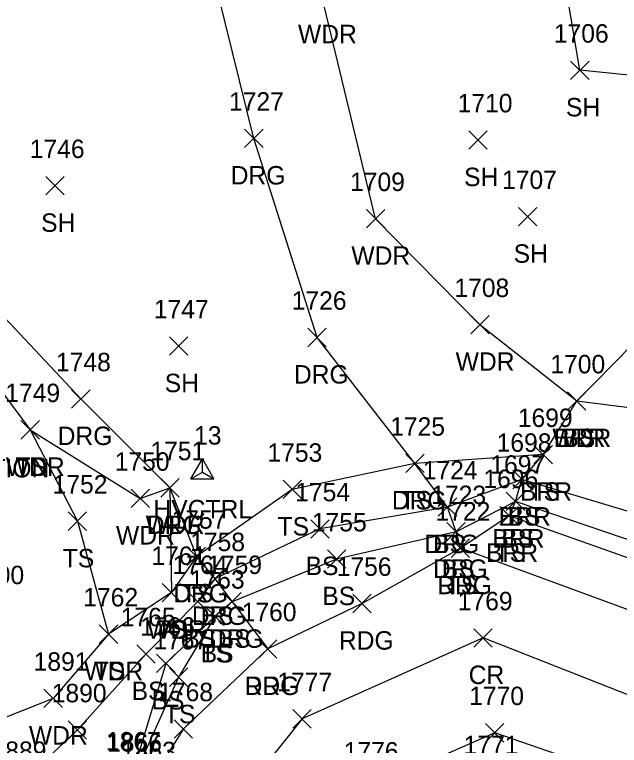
# Model space of a CAD drawing. Extents: x 1600281 to 1602254, y 862855 to 863227.
# Drawn here: x 1602048 to 1602113.6, y 863101.9 to 863181.1 of the extents above; entities that cross this region are included whole.
import ezdxf

# ---------------------------------------------------------------- set-up
doc = ezdxf.new("R2010")
doc.units = 0
for name, color, linetype in [('C_A', 7, 'Continuous'), ('C_I', 7, 'Continuous'), ('CPSM', 7, 'Continuous'), ('L_A', 7, 'Continuous'), ('L_I', 7, 'Continuous'), ('L_TIC', 7, 'Continuous'), ('LABL', 7, 'Continuous'), ('LAWA', 7, 'Continuous'), ('LELB', 7, 'Continuous'), ('LSOGP', 7, 'Continuous'), ('P_A', 7, 'Continuous'), ('P_I', 7, 'Continuous'), ('P_TIC', 7, 'Continuous'), ('PEU', 7, 'Continuous'), ('PRC', 7, 'Continuous'), ('R_A', 7, 'Continuous'), ('R_I', 7, 'Continuous'), ('R_TIC', 7, 'Continuous'), ('RDG', 7, 'Continuous')]:
    doc.layers.add(name, color=color, linetype=linetype)

msp = doc.modelspace()

# ---------------------------------------------------------------- linework, layer by layer
at = {"layer": 'CPSM'}
for p, q in [((1602067.085, 863130.751), (1602068.335, 863132.916)), ((1602069.585, 863130.751), (1602068.335, 863132.916)), ((1602068.336, 863131.472), (1602068.335, 863132.916)), ((1602067.085, 863130.751), (1602068.336, 863131.472)), ((1602068.336, 863131.472), (1602068.336, 863131.472)), ((1602068.336, 863131.472), (1602069.585, 863130.751)), ((1602067.085, 863130.751), (1602069.585, 863130.751))]:
    msp.add_line(p, q, dxfattribs=at)
at = {"layer": 'L_TIC'}
for points in [[(1602108.275, 863174.062), (1602110.275, 863176.062)], [(1602110.275, 863174.062), (1602108.275, 863176.062)], [(1602097.23, 863166.5), (1602099.23, 863168.5)], [(1602099.23, 863166.5), (1602097.23, 863168.5)], [(1602051.363, 863161.543), (1602053.363, 863163.543)], [(1602053.363, 863161.543), (1602051.363, 863163.543)], [(1602086.128, 863157.967), (1602088.128, 863159.967)], [(1602088.128, 863157.967), (1602086.128, 863159.967)], [(1602102.607, 863158.19), (1602104.607, 863160.19)], [(1602104.607, 863158.19), (1602102.607, 863160.19)], [(1602097.439, 863146.474), (1602099.439, 863148.474)], [(1602099.439, 863146.474), (1602097.439, 863148.474)], [(1602064.765, 863144.155), (1602066.765, 863146.155)], [(1602066.765, 863144.155), (1602064.765, 863146.155)], [(1602107.93, 863138.196), (1602109.93, 863140.196)], [(1602109.93, 863138.196), (1602107.93, 863140.196)], [(1602107.93, 863138.196), (1602109.93, 863140.196)], [(1602109.93, 863138.196), (1602107.93, 863140.196)], [(1602107.93, 863138.196), (1602109.93, 863140.196)], [(1602109.93, 863138.196), (1602107.93, 863140.196)], [(1602048.66, 863135.076), (1602050.66, 863137.076)], [(1602050.66, 863135.076), (1602048.66, 863137.076)], [(1602048.66, 863135.076), (1602050.66, 863137.076)], [(1602050.66, 863135.076), (1602048.66, 863137.076)], [(1602104.293, 863132.383), (1602106.293, 863134.383)], [(1602106.293, 863132.383), (1602104.293, 863134.383)], [(1602104.293, 863132.383), (1602106.293, 863134.383)], [(1602106.293, 863132.383), (1602104.293, 863134.383)], [(1602090.394, 863131.436), (1602092.394, 863133.436)], [(1602092.394, 863131.436), (1602090.394, 863133.436)], [(1602101.988, 863129.687), (1602103.988, 863131.687)], [(1602103.988, 863129.687), (1602101.988, 863131.687)], [(1602101.988, 863129.687), (1602103.988, 863131.687)], [(1602103.988, 863129.687), (1602101.988, 863131.687)], [(1602063.822, 863128.779), (1602065.822, 863130.779)], [(1602065.822, 863128.779), (1602063.822, 863130.779)], [(1602077.084, 863128.61), (1602079.084, 863130.61)], [(1602079.084, 863128.61), (1602077.084, 863130.61)], [(1602060.607, 863127.634), (1602062.607, 863129.634)], [(1602062.607, 863127.634), (1602060.607, 863129.634)], [(1602101.3, 863127.31), (1602103.3, 863129.31)], [(1602103.3, 863127.31), (1602101.3, 863129.31)], [(1602101.3, 863127.31), (1602103.3, 863129.31)], [(1602103.3, 863127.31), (1602101.3, 863129.31)], [(1602093.922, 863126.701), (1602095.922, 863128.701)], [(1602095.922, 863126.701), (1602093.922, 863128.701)], [(1602100.608, 863125.756), (1602102.608, 863127.756)], [(1602102.608, 863125.756), (1602100.608, 863127.756)], [(1602100.608, 863125.756), (1602102.608, 863127.756)], [(1602102.608, 863125.756), (1602100.608, 863127.756)], [(1602053.787, 863125.162), (1602055.787, 863127.162)], [(1602055.787, 863125.162), (1602053.787, 863127.162)], [(1602080.093, 863124.324), (1602082.093, 863126.324)], [(1602082.093, 863124.324), (1602080.093, 863126.324)], [(1602094.851, 863124.022), (1602096.851, 863126.022)], [(1602096.851, 863124.022), (1602094.851, 863126.022)], [(1602095.314, 863122.237), (1602097.314, 863124.237)], [(1602097.314, 863122.237), (1602095.314, 863124.237)], [(1602066.689, 863121.351), (1602068.689, 863123.351)], [(1602068.689, 863121.351), (1602066.689, 863123.351)], [(1602081.9, 863121.059), (1602083.9, 863123.059)], [(1602083.9, 863121.059), (1602081.9, 863123.059)], [(1602068.706, 863118.916), (1602070.706, 863120.916)], [(1602070.706, 863118.916), (1602068.706, 863120.916)], [(1602063.976, 863117.423), (1602065.976, 863119.423)], [(1602065.976, 863117.423), (1602063.976, 863119.423)], [(1602063.976, 863117.423), (1602065.976, 863119.423)], [(1602065.976, 863117.423), (1602063.976, 863119.423)], [(1602066.839, 863116.438), (1602068.839, 863118.438)], [(1602068.839, 863116.438), (1602066.839, 863118.438)], [(1602070.558, 863116.437), (1602072.558, 863118.437)], [(1602072.558, 863116.437), (1602070.558, 863118.437)], [(1602068.712, 863114.849), (1602070.712, 863116.849)], [(1602070.712, 863114.849), (1602068.712, 863116.849)], [(1602068.712, 863114.849), (1602070.712, 863116.849)], [(1602070.712, 863114.849), (1602068.712, 863116.849)], [(1602057.16, 863112.919), (1602059.16, 863114.919)], [(1602059.16, 863112.919), (1602057.16, 863114.919)], [(1602057.16, 863112.919), (1602059.16, 863114.919)], [(1602059.16, 863112.919), (1602057.16, 863114.919)], [(1602061.228, 863110.773), (1602063.228, 863112.773)], [(1602063.228, 863110.773), (1602061.228, 863112.773)], [(1602063.38, 863109.746), (1602065.38, 863111.746)], [(1602065.38, 863109.746), (1602063.38, 863111.746)], [(1602064.759, 863108.254), (1602066.759, 863110.254)], [(1602066.759, 863108.254), (1602064.759, 863110.254)], [(1602051.162, 863105.946), (1602053.162, 863107.946)], [(1602053.162, 863105.946), (1602051.162, 863107.946)], [(1602053.778, 863102.527), (1602055.778, 863104.527)], [(1602055.778, 863102.527), (1602053.778, 863104.527)], [(1602053.778, 863102.527), (1602055.778, 863104.527)], [(1602055.778, 863102.527), (1602053.778, 863104.527)]]:
    msp.add_lwpolyline(points, dxfattribs=at)
at = {"layer": 'LABL'}
msp.add_lwpolyline([(1602238.454, 863059.384), (1602199.343, 863071.615), (1602179.647, 863080.082), (1602148.756, 863103.129), (1602128.22, 863117.316), (1602101.608, 863126.756), (1602102.3, 863128.31), (1602102.988, 863130.687), (1602105.293, 863133.383), (1602108.93, 863139.196)], dxfattribs=at)
at = {"layer": 'LAWA'}
msp.add_lwpolyline([(1602117.191, 863138.117), (1602108.93, 863139.196), (1602098.439, 863147.474), (1602087.128, 863158.967), (1602081.34, 863183), (1602074.275, 863197.396), (1602065.047, 863221.998), (1602049.133, 863212.707), (1602032.105, 863201.55), (1602028.2, 863197.002), (1602026.665, 863194.298), (1602025.937, 863190.594), (1602025.234, 863186.894), (1602024.692, 863172.016), (1602032.794, 863158.744), (1602049.66, 863136.076), (1602061.607, 863128.634), (1602064.822, 863129.779), (1602064.976, 863118.423), (1602058.16, 863113.919), (1602052.162, 863106.946), (1602042.214, 863103.013), (1602035.268, 863100.33)], dxfattribs=at)
at = {"layer": 'LELB'}
for points in [[(1602108.93, 863139.196), (1602120.825, 863151.296), (1602125.731, 863162.078), (1602125.538, 863173.403)], [(1602049.66, 863136.076), (1602054.787, 863126.162), (1602058.16, 863113.919)], [(1602105.293, 863133.383), (1602091.394, 863132.436), (1602078.084, 863129.61), (1602067.689, 863122.351), (1602064.976, 863118.423)], [(1602242.076, 863077.12), (1602206.814, 863090.25), (1602186.388, 863095.467), (1602152.125, 863112.741), (1602132.318, 863121.88), (1602102.988, 863130.687), (1602094.922, 863127.701), (1602081.093, 863125.324), (1602069.706, 863119.916), (1602067.839, 863117.438), (1602062.228, 863111.773), (1602054.778, 863103.527)], [(1602241.548, 863072.298), (1602203.833, 863084.044), (1602184.904, 863092.774), (1602150.824, 863109.068), (1602129.545, 863119.041), (1602102.3, 863128.31), (1602095.851, 863125.022), (1602082.9, 863122.059), (1602071.558, 863117.437), (1602069.712, 863115.849), (1602064.38, 863110.746), (1602060.621, 863098.298)], [(1602101.608, 863126.756), (1602096.314, 863123.237)], [(1602069.712, 863115.849), (1602065.759, 863109.254), (1602060.799, 863098.174)], [(1602037.877, 863092.461), (1602048.175, 863097.278), (1602054.778, 863103.527)]]:
    msp.add_lwpolyline(points, dxfattribs=at)
at = {"layer": 'LSOGP'}
msp.add_lwpolyline([(1602125.538, 863173.403), (1602109.275, 863175.062), (1602106.49, 863191.711), (1602074.275, 863197.396), (1602065.047, 863221.998), (1602049.133, 863212.707), (1602032.105, 863201.55), (1602028.2, 863197.002), (1602026.665, 863194.298), (1602025.937, 863190.594), (1602025.234, 863186.894), (1602007.362, 863182.606), (1601999.337, 863179.726), (1601966.602, 863191.094), (1601957.22, 863184.57), (1601933.606, 863167.485), (1601930.07, 863156.542), (1601924.031, 863153.206)], dxfattribs=at)
at = {"layer": 'P_TIC'}
for points in [[(1602095.314, 863122.237), (1602097.314, 863124.237)], [(1602097.314, 863122.237), (1602095.314, 863124.237)], [(1602084.65, 863116.237), (1602086.65, 863118.237)], [(1602086.65, 863116.237), (1602084.65, 863118.237)], [(1602097.781, 863112.504), (1602099.781, 863114.504)], [(1602099.781, 863112.504), (1602097.781, 863114.504)], [(1602074.424, 863111.315), (1602076.424, 863113.315)], [(1602076.424, 863111.315), (1602074.424, 863113.315)], [(1602078.146, 863103.728), (1602080.146, 863105.728)], [(1602080.146, 863103.728), (1602078.146, 863105.728)], [(1602065.282, 863102.641), (1602067.282, 863104.641)], [(1602067.282, 863102.641), (1602065.282, 863104.641)], [(1602099.046, 863102.218), (1602101.046, 863104.218)], [(1602101.046, 863102.218), (1602099.046, 863104.218)]]:
    msp.add_lwpolyline(points, dxfattribs=at)
at = {"layer": 'PEU'}
for points in [[(1602239.323, 863063.193), (1602201.856, 863077.578), (1602181.734, 863084.138), (1602148.756, 863103.129), (1602126.101, 863112.297), (1602096.314, 863123.237), (1602085.65, 863117.237), (1602075.424, 863112.315), (1602066.282, 863103.641), (1602062.254, 863097.245), (1602069.562, 863092.761), (1602076.187, 863089.042)], [(1602235.306, 863048.086), (1602195.245, 863059.48), (1602172.509, 863066.536), (1602139.216, 863086.847), (1602117.278, 863097.261), (1602100.046, 863103.218), (1602086.406, 863097.204), (1602076.187, 863089.042)]]:
    msp.add_lwpolyline(points, dxfattribs=at)
at = {"layer": 'PRC'}
msp.add_lwpolyline([(1602236.396, 863054.637), (1602198.655, 863067.234), (1602177.306, 863075.301), (1602143.813, 863093.879), (1602121.553, 863104.551), (1602098.781, 863113.504), (1602079.146, 863104.728), (1602069.562, 863092.761)], dxfattribs=at)
at = {"layer": 'R_TIC'}
for points in [[(1602072.916, 863166.679), (1602074.916, 863168.679)], [(1602074.916, 863166.679), (1602072.916, 863168.679)], [(1602079.771, 863145.091), (1602081.771, 863147.091)], [(1602081.771, 863145.091), (1602079.771, 863147.091)], [(1602054.152, 863138.425), (1602056.152, 863140.425)], [(1602056.152, 863138.425), (1602054.152, 863140.425)], [(1602090.394, 863131.436), (1602092.394, 863133.436)], [(1602092.394, 863131.436), (1602090.394, 863133.436)], [(1602063.822, 863128.779), (1602065.822, 863130.779)], [(1602065.822, 863128.779), (1602063.822, 863130.779)], [(1602093.922, 863126.701), (1602095.922, 863128.701)], [(1602095.922, 863126.701), (1602093.922, 863128.701)], [(1602094.851, 863124.022), (1602096.851, 863126.022)], [(1602096.851, 863124.022), (1602094.851, 863126.022)], [(1602095.314, 863122.237), (1602097.314, 863124.237)], [(1602097.314, 863122.237), (1602095.314, 863124.237)], [(1602066.689, 863121.351), (1602068.689, 863123.351)], [(1602068.689, 863121.351), (1602066.689, 863123.351)], [(1602068.706, 863118.916), (1602070.706, 863120.916)], [(1602070.706, 863118.916), (1602068.706, 863120.916)], [(1602070.558, 863116.437), (1602072.558, 863118.437)], [(1602072.558, 863116.437), (1602070.558, 863118.437)], [(1602074.424, 863111.315), (1602076.424, 863113.315)], [(1602076.424, 863111.315), (1602074.424, 863113.315)]]:
    msp.add_lwpolyline(points, dxfattribs=at)
at = {"layer": 'RDG'}
msp.add_lwpolyline([(1602096.314, 863123.237), (1602095.851, 863125.022), (1602094.922, 863127.701), (1602091.394, 863132.436), (1602080.771, 863146.091), (1602073.916, 863167.679), (1602068.483, 863189.633), (1602064.495, 863203.426), (1602049.949, 863202.722), (1602036.232, 863194.16), (1602033.599, 863191.505), (1602032.5, 863189.602), (1602031.273, 863187.553), (1602028.658, 863173.712), (1602035.777, 863160.035), (1602055.152, 863139.425), (1602064.822, 863129.779), (1602067.689, 863122.351), (1602069.706, 863119.916), (1602071.558, 863117.437), (1602075.424, 863112.315)], dxfattribs=at)

# ---------------------------------------------------------------- texts
at = {"layer": 'C_A'}
msp.add_text('HVCTRL', height=2, dxfattribs=at).set_placement((1602063.028, 863126.472))
at = {"layer": 'C_I'}
msp.add_text('13', height=2, dxfattribs=at).set_placement((1602067.438, 863134.472))
at = {"layer": 'L_A'}
for s, p in [('WDR', (1602078.702, 863178)), ('SH', (1602107.763, 863170.062)), ('SH', (1602096.718, 863162.5)), ('SH', (1602050.851, 863157.543)), ('WDR', (1602084.491, 863153.967)), ('SH', (1602102.095, 863154.19)), ('WDR', (1602095.801, 863142.474)), ('SH', (1602064.253, 863140.155)), ('WDR', (1602106.292, 863134.196)), ('BRR', (1602106.418, 863134.196)), ('BS', (1602107.371, 863134.196)), ('FOUNDATION', (1602034.062, 863130.91)), ('WDR', (1602047.022, 863131.076)), ('TS', (1602048.069, 863131.076)), ('BRR', (1602102.781, 863128.383)), ('TS', (1602103.703, 863128.383)), ('TS', (1602089.803, 863127.436)), ('BRR', (1602100.476, 863125.687)), ('BS', (1602101.429, 863125.687)), ('WDR', (1602062.184, 863124.779)), ('TS', (1602076.493, 863124.61)), ('WDR', (1602058.969, 863123.634)), ('BRR', (1602099.788, 863123.31)), ('BS', (1602100.741, 863123.31)), ('BS', (1602093.363, 863122.701)), ('BRR', (1602099.096, 863121.756)), ('TS', (1602100.017, 863121.756)), ('TS', (1602053.196, 863121.162)), ('BS', (1602079.534, 863120.324)), ('BS', (1602094.292, 863120.022)), ('TS', (1602094.723, 863118.237)), ('TS', (1602066.099, 863117.351)), ('BS', (1602081.341, 863117.059)), ('BS', (1602068.147, 863114.916)), ('WDR', (1602062.338, 863113.423)), ('TS', (1602063.386, 863113.423)), ('BS', (1602066.28, 863112.438)), ('BS', (1602069.999, 863112.437)), ('TS', (1602068.122, 863110.849)), ('BS', (1602068.153, 863110.849)), ('WDR', (1602055.522, 863108.919)), ('TS', (1602056.57, 863108.919)), ('BS', (1602060.669, 863106.773)), ('BS', (1602062.821, 863105.746)), ('TS', (1602064.168, 863104.254)), ('WDR', (1602049.524, 863101.946))]:
    msp.add_text(s, height=2, dxfattribs=at).set_placement(p)
at = {"layer": 'L_I'}
for s, p in [('1706', (1602106.448, 863178.062)), ('1710', (1602096.018, 863170.5)), ('1746', (1602049.615, 863165.543)), ('1709', (1602084.349, 863161.967)), ('1707', (1602100.835, 863162.19)), ('1708', (1602095.667, 863150.474)), ('1747', (1602063.072, 863148.155)), ('1700', (1602106.072, 863142.196)), ('1700', (1602106.072, 863142.196)), ('1700', (1602106.072, 863142.196)), ('1749', (1602046.959, 863139.076)), ('1749', (1602046.959, 863139.076)), ('1699', (1602102.545, 863136.383)), ('1699', (1602102.545, 863136.383)), ('1725', (1602088.701, 863135.436)), ('1698', (1602100.247, 863133.687)), ('1698', (1602100.247, 863133.687)), ('1751', (1602062.696, 863132.779)), ('1753', (1602075.391, 863132.61)), ('1750', (1602058.827, 863131.634)), ('1697', (1602099.56, 863131.31)), ('1697', (1602099.56, 863131.31)), ('1724', (1602092.229, 863130.701)), ('1696', (1602098.812, 863129.756)), ('1696', (1602098.812, 863129.756)), ('1752', (1602052.094, 863129.162)), ('1754', (1602078.4, 863128.324)), ('1723', (1602093.158, 863128.022)), ('1722', (1602093.621, 863126.237)), ('1757', (1602064.996, 863125.351)), ('1755', (1602080.208, 863125.059)), ('1758', (1602067.013, 863122.916)), ('1761', (1602062.803, 863121.423)), ('1761', (1602062.803, 863121.423)), ('1764', (1602065.099, 863120.438)), ('1759', (1602068.857, 863120.437)), ('1900', (1602043.062, 863119.332)), ('1763', (1602066.972, 863118.849)), ('1763', (1602066.972, 863118.849)), ('1762', (1602055.42, 863116.919)), ('1762', (1602055.42, 863116.919)), ('1765', (1602059.487, 863114.773)), ('1766', (1602061.584, 863113.746)), ('1767', (1602063.018, 863112.254)), ('1891', (1602050.036, 863109.946)), ('1890', (1602051.999, 863106.527)), ('1890', (1602051.999, 863106.527)), ('1867', (1602057.881, 863101.298)), ('1866', (1602058.003, 863101.174)), ('1771', (1602096.667, 863100.894)), ('1889', (1602045.475, 863100.278))]:
    msp.add_text(s, height=2, dxfattribs=at).set_placement(p)
at = {"layer": 'P_A'}
for s, p in [('RDG', (1602093.802, 863118.237)), ('RDG', (1602083.138, 863112.237)), ('CR', (1602097.214, 863108.504)), ('RDG', (1602072.912, 863107.315))]:
    msp.add_text(s, height=2, dxfattribs=at).set_placement(p)
at = {"layer": 'P_I'}
for s, p in [('1722', (1602093.621, 863126.237)), ('1756', (1602082.902, 863120.237)), ('1769', (1602096.033, 863116.504)), ('1760', (1602072.597, 863115.315)), ('1777', (1602076.453, 863107.728)), ('1768', (1602063.542, 863106.641)), ('1770', (1602097.267, 863106.218)), ('1863', (1602059.514, 863100.245)), ('1776', (1602083.658, 863100.204))]:
    msp.add_text(s, height=2, dxfattribs=at).set_placement(p)
at = {"layer": 'R_A'}
for p in [(1602071.405, 863162.679), (1602078.259, 863141.091), (1602052.64, 863134.425), (1602088.882, 863127.436), (1602062.31, 863124.779), (1602092.41, 863122.701), (1602093.339, 863120.022), (1602093.802, 863118.237), (1602065.177, 863117.351), (1602067.194, 863114.916), (1602069.046, 863112.437), (1602072.912, 863107.315)]:
    msp.add_text('DRG', height=2, dxfattribs=at).set_placement(p)
at = {"layer": 'R_I'}
for s, p in [('1727', (1602071.223, 863170.679)), ('1726', (1602078.023, 863149.091)), ('1748', (1602052.459, 863142.425)), ('1725', (1602088.701, 863135.436)), ('1751', (1602062.696, 863132.779)), ('1724', (1602092.229, 863130.701)), ('1723', (1602093.158, 863128.022)), ('1722', (1602093.621, 863126.237)), ('1757', (1602064.996, 863125.351)), ('1758', (1602067.013, 863122.916)), ('1759', (1602068.857, 863120.437)), ('1760', (1602072.597, 863115.315)), ('1863', (1602059.514, 863100.245))]:
    msp.add_text(s, height=2, dxfattribs=at).set_placement(p)

doc.saveas('drawing.dxf')
